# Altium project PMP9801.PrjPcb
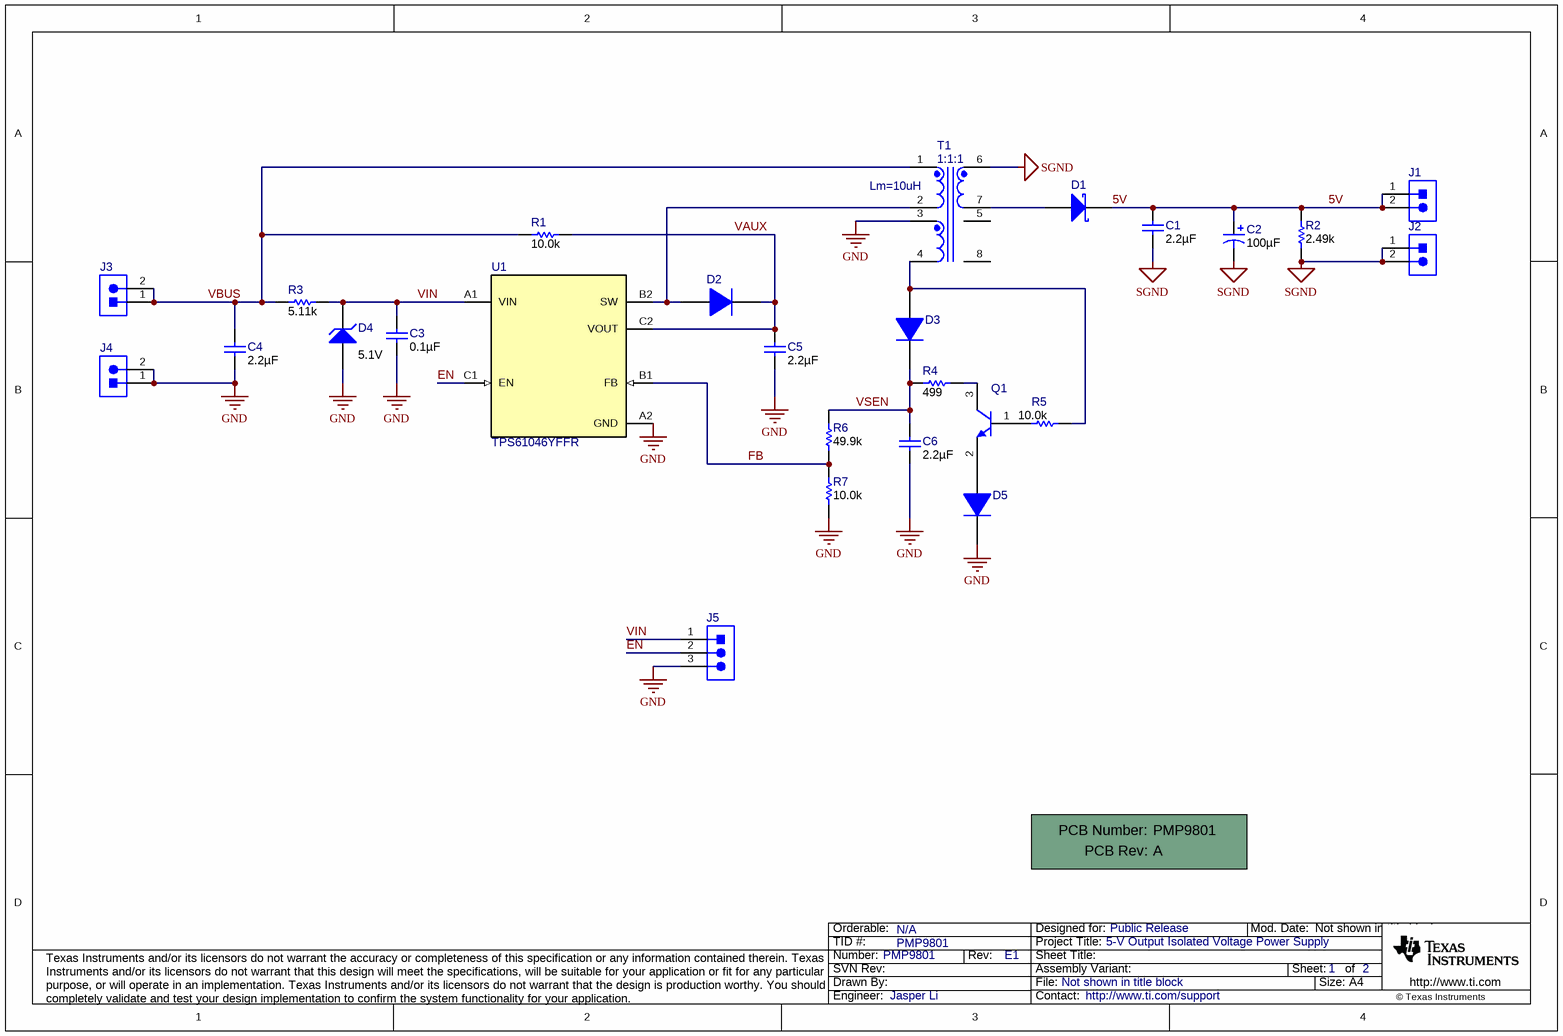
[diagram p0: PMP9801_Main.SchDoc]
EVM_Orderable: N/A; PCB_Layout: Jasper; PCB_Rev: A; PRJ_Customer: Public Release; PRJ_Engineer: Jasper Li; PRJ_Number: PMP9801; PRJ_Title: 5-V Output Isolated Voltage Power Supply; SCH_Rev: E1; TechSupport: http://www.ti.com/support; TID: PMP9801
1 sheet, 27 parts. Net scope: global (net labels, ports and power ports of the same name join across sheets).
Board file: PMP9801.PcbDoc

## Sheet PMP9801_Main.SchDoc
size A4; Date: Not shown in title block; ApprovedBy: Not shown in title block; CheckedBy: Not shown in title block; Author: Not shown in title block; CompanyName: Not shown in title block; Engineer: Not shown in title block; Organization: Not shown in title block; Address1: Not shown in title block; Address2: Not shown in title block; Address3: Not shown in title block; Address4: Not shown in title block; DocumentNumber: 1; Revision: Use project parameter SCH_Rev; SheetNumber: 1; SheetTotal: 2; PageSetup: Record=PageOptions¦CenterHorizontal=True¦CenterVertical=True¦PrintScale=0.91¦XCorrection=1.00¦YCorrection=1.00¦PrintKind=0¦BorderSize=5000000¦LeftOffset=0¦BottomOffset=0¦Orientation=2¦PaperLength=1000¦PaperWidth=1000¦Scale=100¦PaperSource=15¦PrintQuality=600¦MediaType=1¦DitherType=10¦PrintScaleMode=1¦PaperKind=Letter

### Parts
!PCB1  Printed Circuit Board  (value not drawn)  (mechanical)
C1  ValueDisplayed: 2.2µF  [0603]  (hidden comment: GRM188R6YA225KA12D)
C2  ValueDisplayed: 100µF  [CAPPR250W50D630H1120]  (hidden comment: EEU-EB1E101S)
C3  ValueDisplayed: 0.1µF  [0603]  (hidden comment: GRM188R61C104KA01D)
C4  ValueDisplayed: 2.2µF  [0603]  (hidden comment: GRM188R6YA225KA12D)
C5  ValueDisplayed: 2.2µF  [0603]  (hidden comment: GRM188R6YA225KA12D)
C6  ValueDisplayed: 2.2µF  [0603]  (hidden comment: GRM188R6YA225KA12D)
D1  MBR0540T1G  [SOD-123]  (value not drawn)
D2  1N4148W-TP  [SOD-123]  (value not drawn)
D3  1N4148W-TP  [SOD-123]  (value not drawn)
D4  value 5.1V  [sod-323]  (hidden comment: CMDZ5L1 TR)
D5  1N4148W-TP  [SOD-123]  (value not drawn)
J1  TSW-102-07-G-S  [TSW-102-07-G-S]  (value not drawn)
J2  TSW-102-07-G-S  [TSW-102-07-G-S]  (value not drawn)
J3  TSW-102-07-G-S  [TSW-102-07-G-S]  (value not drawn)
J4  TSW-102-07-G-S  [TSW-102-07-G-S]  (value not drawn)
J5  TSW-103-07-G-S  [TSW-103-07-G-S]  (value not drawn)
Q1  MMBT3904  [SOT-23]  (value not drawn)
R1  ValueDisplayed: 10.0k  [0603]  (hidden comment: RC0603FR-0710KL)
R2  ValueDisplayed: 2.49k  [0603]  (hidden comment: RC0603FR-072K49L)
R3  ValueDisplayed: 5.11k  [0603]  (hidden comment: CRCW06035K11FKEA)
R4  ValueDisplayed: 499  [0603]  (hidden comment: RC0603FR-07499RL)
R5  ValueDisplayed: 10.0k  [0603]  (hidden comment: RC0603FR-0710KL)
R6  ValueDisplayed: 49.9k  [0603]  (hidden comment: CRCW060349K9FKEA)
R7  ValueDisplayed: 10.0k  [0603]  (hidden comment: RC0603FR-0710KL)
T1  Used in BOM report  [CoilCraft_10uH]  (value not drawn)
U1  TPS61046YFFR  [YFF0006AAAA]

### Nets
GND: C3.2 C4.2 C5.2 C6.2 D4.2(A) D5.1(K) J4.1 J4.2 J5.3 R7.2 T1.3 U1.A2(GND)
SGND: C1.2 C2.2(-) J2.1 J2.2 R2.1 T1.6
5V: C1.1 C2.1(+) D1.1(K) J1.1 J1.2 R2.2
EN: J5.2 U1.C1(EN)
FB: R6.1 R7.1 U1.B1(FB)
VAUX: C5.1 D2.1(K) R1.1 U1.C2(VOUT)
VBUS: C4.1 J3.1 J3.2 R1.2 R3.1 T1.1
VIN: C3.1 D4.1(K) J5.1 R3.2 U1.A1(VIN)
VSEN: C6.1 D3.1(K) R4.2 R6.2
NetD1_2: D1.2(A) T1.7
NetD2_2: D2.2(A) T1.2 U1.B2(SW)
NetD3_2: D3.2(A) R5.1 T1.4
NetD5_2: D5.2(A) Q1.2(E)
NetQ1_1: Q1.1(B) R5.2
NetQ1_3: Q1.3(C) R4.1

Not connected (* = marked no-connect by the designer): T1 5 8

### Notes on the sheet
- (near T1) 1:1:1
- (near T1) Lm=10uH

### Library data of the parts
!PCB1 = PCB: Manufacturer: Any; PartNumber: PMP9801; SymbolCreator: a0412235
C1 C4-C6 = GRM188R6YA225KA12D: CAP, CERM, 2.2 µF, 35 V, +/- 10%, X5R, 0603; Manufacturer: MuRata; Polarized: N; CompType: Capacitor; Value: 2.2uF; U/M: EA; Cap_F: 0.0000022; Tolerance_%: 10; Value1: Unknown; VDC_V: 35; Value2: 35V; TaMin_C: -55; TaMax_C: 85; AEC Category: Q200
C2 = EEU-EB1E101S: CAP, AL, 100 µF, 25 V, +/- 20%, TH; Manufacturer: Panasonic; Polarized: Y; CompType: Capacitor; Value: 100uF; U/M: EA; Cap_F: 0.0001; Tolerance_%: 20; Value1: Unknown; VDC_V: 25; Value2: 25V; IRMS_A: 0.095; TaMin_C: -40; TaMax_C: 105; Cap_Case: Radial 6.3x11.2; AEC Category: Q200; AEC Qualified: N
C3 = GRM188R61C104KA01D: CAP, CERM, 0.1 µF, 16 V, +/- 10%, X5R, 0603; Manufacturer: MuRata; Polarized: N; CompType: Capacitor; Value: 0.1uF; U/M: EA; Cap_F: 0.0000001; Tolerance_%: 10; Value1: Unknown; VDC_V: 16; Value2: 16V; TaMin_C: -55; TaMax_C: 85; AEC Category: Q200
D1 = MBR0540T1G: Diode, Schottky, 40 V, 0.5 A, SOD-123; Manufacturer: ON Semiconductor; U/M: EA; Vf_V: 0.51; Value: 40V; Value1: 0.5A; Value2: 0.51V; Io_A: 0.5; Vr_V: 40; TJmax_C: 150; RJC_CperW: 118; AEC Category: Q101
D2 D3 D5 = 1N4148W-TP: Diode, Switching, 100 V, 0.15 A, SOD-123; Manufacturer: Micro Commercial Components; U/M: EA; Vf_V: 1.25; Value: 100V; Value1: 0.15A; Value2: 1.25V; Io_A: 0.15; Vr_V: 100; TJmax_C: 150; AEC Category: Q101
D4 = CMDZ5L1 TR: Diode, Zener, 5.1 V, 250 mW, SOD-323; Manufacturer: Central Semiconductor; SymbolCreator: a0412235; U/M: EA; Power_W: 0.25; Vz_V: 5.1; Value1: 0.25W; RJA_CperW: 500; AEC Category: Q101
J1-J4 = TSW-102-07-G-S: Header, 100mil, 2x1, Gold, TH; Manufacturer: Samtec; SymbolCreator: a0412235; Pitch_mm: 2.54; Gender: Male; Shrouded: N; Row_Count: 1; Current_A: 6.3; Voltage_V: 550; Cert_CSA: Y
J5 = TSW-103-07-G-S: Header, 100mil, 3x1, Gold, TH; Manufacturer: Samtec; SymbolCreator: a0799628; Pitch_mm: 2.54; Gender: Male; Shrouded: N; Row_Count: 1; Current_A: 6.3; Voltage_V: 550; Cert_CSA: Y
Q1 = MMBT3904, Fairchild Semiconductor: Transistor, NPN, 40 V, 0.2 A, SOT-23; CompType: BJT; PNP: 0; NPN: 1; Vceo_V: 40; Vcesat1_V: 0.2; Value: 40 V; Value1: 0.2 A; HfeMax: 300; TaMin_C: -55; TaMax_C: 150; U/M: EA; AEC Category: Q101
R1 R5 R7 = RC0603FR-0710KL: RES, 10.0 k, 1%, 0.1 W, 0603; Manufacturer: Yageo America; CompType: Resistor; Value: 10.0k; Res_ohm: 10000; Value_Code: 10k0; Tolerance_%: 1; Power_W: 0.1; Value2: 0.1W; VDC_V: 150; TempCo: 200 ppm/C; EIA_Code: E96; U/M: EA; AEC Category: Q200; SizeArea_mm2: 1.28; SizeX_mm: 1.6; SizeY_mm: 0.8
R2 = RC0603FR-072K49L: RES, 2.49 k, 1%, 0.1 W, 0603; Manufacturer: Yageo America; CompType: Resistor; Value: 2.49k; Res_ohm: 2490; Value_Code: 2k49; Tolerance_%: 1; Power_W: 0.1; Value2: 0.1W; VDC_V: 150; TempCo: 200 ppm/C; EIA_Code: E96; U/M: EA; AEC Category: Q200; SizeArea_mm2: 1.28; SizeX_mm: 1.6; SizeY_mm: 0.8
R3 = CRCW06035K11FKEA: RES, 5.11 k, 1%, 0.1 W, 0603; Manufacturer: Vishay-Dale; CompType: Resistor; Value: 5.11k; Res_ohm: 5110; Value_Code: 5k11; Tolerance_%: 1; Power_W: 0.1; Value2: 0.1W; VDC_V: 75; TempCo: 100 ppm/C; EIA_Code: E96; U/M: EA; AEC Category: Q200; SizeArea_mm2: 1.28; SizeX_mm: 1.6; SizeY_mm: 0.8
R4 = RC0603FR-07499RL: RES, 499, 1%, 0.1 W, 0603; Manufacturer: Yageo America; CompType: Resistor; Value: 499; Value_Code: 499R; Tolerance_%: 1; Power_W: 0.1; Value2: 0.1W; VDC_V: 150; TempCo: 200 ppm/C; EIA_Code: E96; U/M: EA; AEC Category: Q200; SizeArea_mm2: 1.28; SizeX_mm: 1.6; SizeY_mm: 0.8
R6 = CRCW060349K9FKEA: RES, 49.9 k, 1%, 0.1 W, 0603; Manufacturer: Vishay-Dale; CompType: Resistor; Value: 49.9k; Res_ohm: 49900; Value_Code: 49k9; Tolerance_%: 1; Power_W: 0.1; Value2: 0.1W; VDC_V: 75; TempCo: 100 ppm/C; EIA_Code: E96; U/M: EA; AEC Category: Q200; SizeArea_mm2: 1.28; SizeX_mm: 1.6; SizeY_mm: 0.8
T1 = CoilCraft_10uH_Transformer: SymbolVersion: use current date i.e. 2008-05-20; SymbolCreator: Use a-id; CompType: Used in some BOM reports.  Useful for finding later.; U/M: EA, IN, or GM
U1 = TPS61046YFFR: 28-V Output Voltage Boost Converter in WCSP Package, YFF0006AAAA; Alternate PartNumber: TPS61046YFFT; Manufacturer: Texas Instruments; SymbolCreator: Altium; CompType: IC; U/M: EA

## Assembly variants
001: all parts fitted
